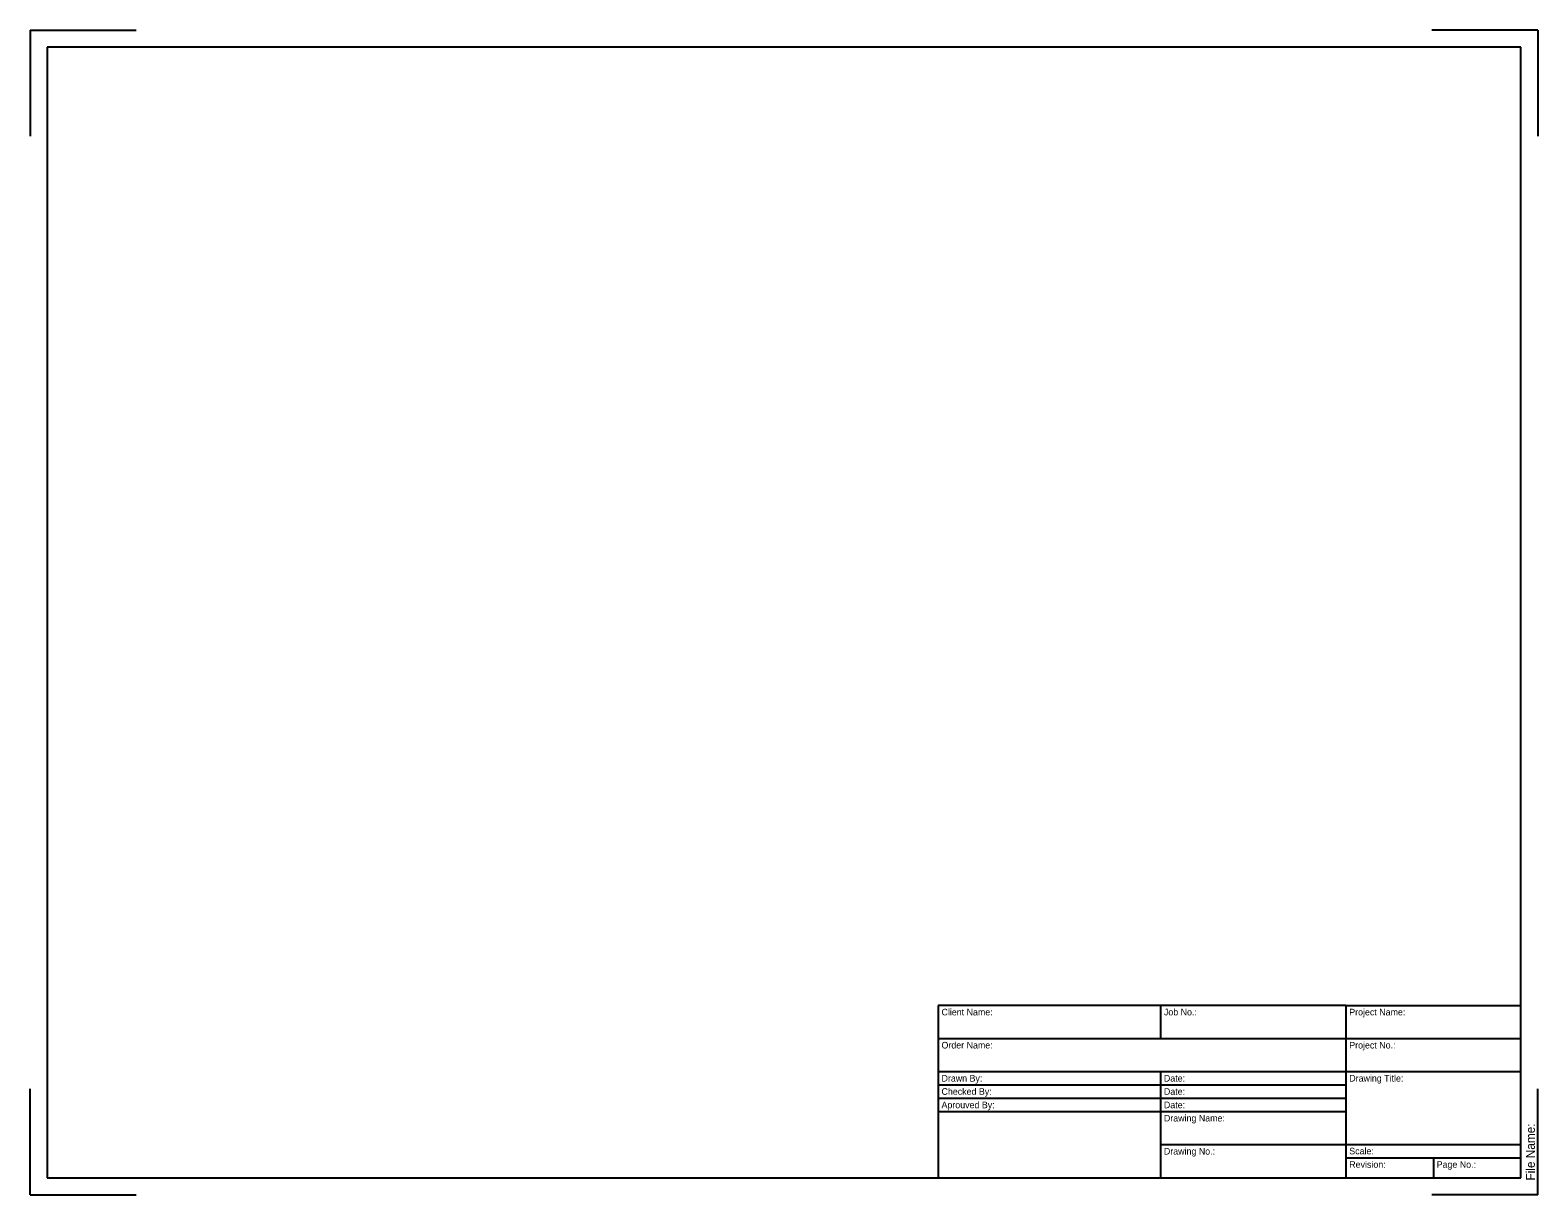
# Model space of a CAD drawing. Extents: x 0 to 0.917, y 0 to 0.708.
import ezdxf

# ---------------------------------------------------------------- set-up
doc = ezdxf.new("R2010")
doc.units = 0
doc.layers.add('STSF-BORDER', color=7, linetype='Continuous')

msp = doc.modelspace()

# ---------------------------------------------------------------- linework, layer by layer
at = {"layer": 'STSF-BORDER'}
for p, q in [((0, 0.70833), (0, 0.64394)), ((0, 0.70833), (0.06439, 0.70833)), ((0.91667, 0.70833), (0.85227, 0.70833)), ((0.91667, 0.70833), (0.91667, 0.64394)), ((0.01042, 0.69792), (0.01042, 0.01042)), ((0.90625, 0.69792), (0.01042, 0.69792)), ((0.90625, 0.01042), (0.90625, 0.69792)), ((0.55208, 0.11517), (0.55208, 0.01042)), ((0.8, 0.11517), (0.55208, 0.11517)), ((0.68731, 0.11517), (0.68731, 0.09505)), ((0.8, 0.11517), (0.90625, 0.11517)), ((0.8, 0.11517), (0.8, 0.01042)), ((0.55208, 0.09505), (0.8, 0.09505)), ((0.8, 0.09505), (0.90625, 0.09505)), ((0.55208, 0.07492), (0.8, 0.07492)), ((0.68731, 0.07492), (0.68731, 0.01042)), ((0.8, 0.07492), (0.90625, 0.07492)), ((0, 0), (0, 0.06439)), ((0.55208, 0.06687), (0.68731, 0.06687)), ((0.68731, 0.06687), (0.8, 0.06687)), ((0.91667, 0), (0.91667, 0.06439)), ((0.55208, 0.05883), (0.68731, 0.05883)), ((0.68731, 0.05883), (0.8, 0.05883)), ((0.55208, 0.05066), (0.68731, 0.05066)), ((0.68731, 0.05066), (0.8, 0.05066)), ((0.68731, 0.03054), (0.8, 0.03054)), ((0.8, 0.03065), (0.90625, 0.03065)), ((0.8, 0.0226), (0.90625, 0.0226)), ((0.85313, 0.0226), (0.85313, 0.01042)), ((0.01042, 0.01042), (0.90625, 0.01042)), ((0, 0), (0.06439, 0)), ((0.91667, 0), (0.85227, 0))]:
    msp.add_line(p, q, dxfattribs=at)

# ---------------------------------------------------------------- texts
for s, height, p in [('Client Name:', 0.0040246, (0.5541, 0.10913)), ('Job No.:', 0.004025, (0.68932, 0.10913)), ('Project Name:', 0.0040246, (0.80201, 0.10913)), ('Order Name:', 0.0040246, (0.5541, 0.08901)), ('Project No.:', 0.0040246, (0.80201, 0.08901)), ('Checked By:', 0.0040246, (0.5541, 0.06084)), ('Drawn By:', 0.004025, (0.5541, 0.06889)), ('Date:', 0.004025, (0.68932, 0.06889)), ('Date:', 0.004025, (0.68932, 0.06084)), ('Drawing Title:', 0.0040246, (0.80201, 0.06889)), ('Aprouved By:', 0.0040246, (0.5541, 0.05268)), ('Date:', 0.004025, (0.68932, 0.05268)), ('Drawing Name:', 0.0040246, (0.68932, 0.04463)), ('Drawing No.:', 0.0040246, (0.68932, 0.0245)), ('Scale:', 0.004025, (0.80201, 0.02462)), ('Revision:', 0.004025, (0.80201, 0.01645)), ('Page No.:', 0.004025, (0.85514, 0.01645))]:
    msp.add_text(s, height=height, dxfattribs=at).set_placement(p)
msp.add_text('File Name:', height=0.005366, rotation=90, dxfattribs=at).set_placement((0.91484, 0.00872))

doc.saveas('drawing.dxf')
